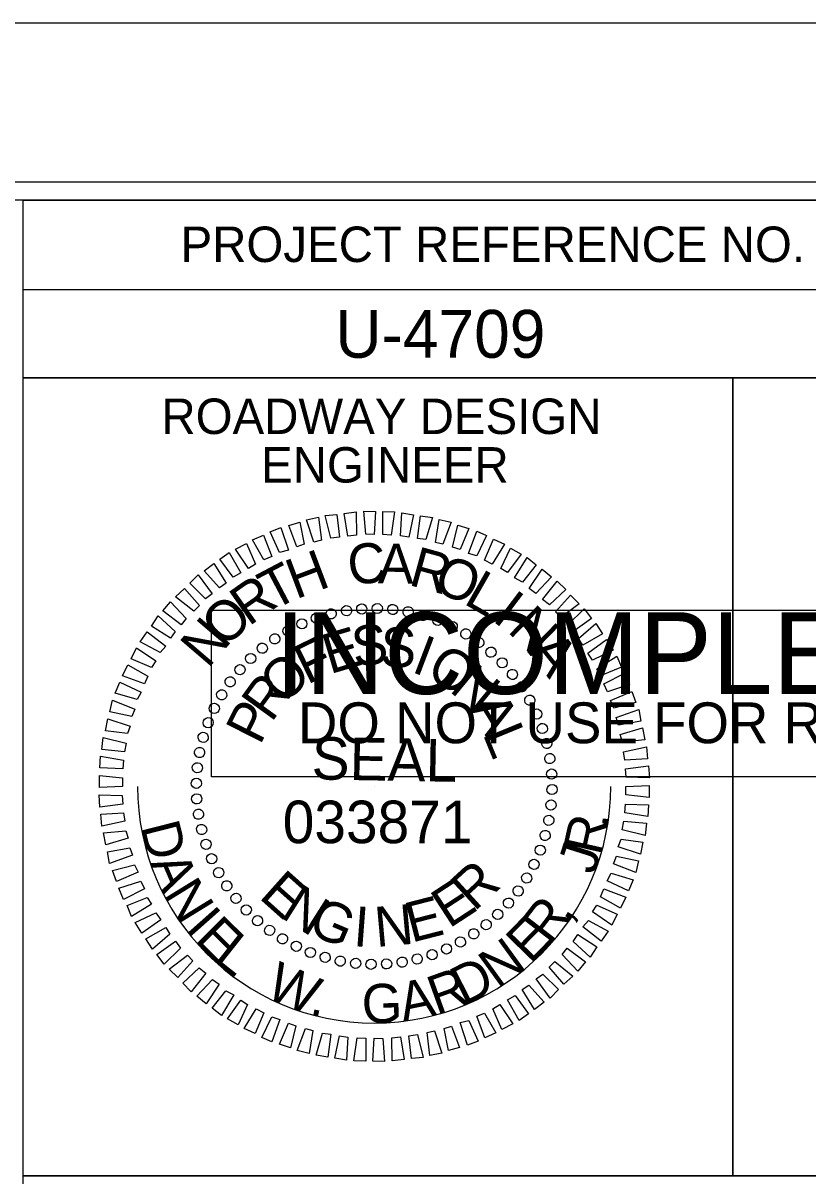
# Model space of a CAD drawing. Extents: x 958711 to 962106, y 831169 to 840840.
# Drawn here: x 960177.7 to 960288.4, y 835779.9 to 835942.4 of the extents above; entities that cross this region are included whole.
import ezdxf

# ---------------------------------------------------------------- set-up
doc = ezdxf.new("R2010")
doc.units = 0
for name, color, linetype in [('Scratch_Level_0', 7, 'Continuous'), ('Sheet Data Field CELL', 7, 'Continuous'), ('Sheet Plot Border Inside CELL', 7, 'Continuous'), ('Sheet Plot Border Outside CELL', 7, 'Continuous'), ('Sheet Professional Seal CELL', 7, 'Continuous'), ('Sheet Profile Grid Minor CELL', 7, 'Continuous'), ('Sheet Sticker Exception Certification CELL', 7, 'Continuous'), ('Sheet Sticker Incomplete CELL', 7, 'Continuous'), ('Sheet Typical CELL', 7, 'Continuous')]:
    doc.layers.add(name, color=color, linetype=linetype)

msp = doc.modelspace()

# ---------------------------------------------------------------- linework, layer by layer
at = {"layer": 'Scratch_Level_0'}
msp.add_arc((960227.25, 835834.78), 33.36, 180, 360, dxfattribs=at)
at = {"layer": 'Sheet Plot Border Inside CELL'}
msp.add_lwpolyline([(960390.3, 835919.97), (958723.8, 835919.97), (958723.8, 834864.87), (960390.3, 834864.87)], close=True, dxfattribs=at)
at = {"layer": 'Sheet Plot Border Outside CELL'}
msp.add_lwpolyline([(960394.8, 835942.42), (958710.8, 835942.42), (958710.8, 834842.42), (960394.8, 834842.42)], close=True, dxfattribs=at)
at = {"layer": 'Sheet Professional Seal CELL'}
for p, q in [((960223.35, 835859.53), (960223.35, 835859.53)), ((960225.5, 835859.83), (960225.5, 835859.83)), ((960227.7, 835859.88), (960227.7, 835859.88)), ((960229.9, 835859.73), (960229.9, 835859.73)), ((960232.05, 835859.38), (960232.05, 835859.38)), ((960219.05, 835858.53), (960219.05, 835858.53)), ((960221.15, 835859.13), (960221.15, 835859.13)), ((960234.15, 835858.93), (960234.15, 835858.93)), ((960236.25, 835858.23), (960236.25, 835858.23)), ((960215.1, 835856.73), (960215.1, 835856.73)), ((960217.05, 835857.73), (960217.05, 835857.73)), ((960238.25, 835857.33), (960238.25, 835857.33)), ((960240.2, 835856.33), (960240.2, 835856.33)), ((960213.2, 835855.58), (960213.2, 835855.58)), ((960242, 835855.08), (960242, 835855.08)), ((960211.45, 835854.33), (960211.45, 835854.33)), ((960243.75, 835853.73), (960243.75, 835853.73)), ((960208.3, 835851.28), (960208.3, 835851.28)), ((960209.8, 835852.83), (960209.8, 835852.83)), ((960245.3, 835852.23), (960245.3, 835852.23)), ((960246.8, 835850.58), (960246.8, 835850.58)), ((960206.95, 835849.53), (960206.95, 835849.53)), ((960248.05, 835848.83), (960248.05, 835848.83)), ((960205.7, 835847.73), (960205.7, 835847.73)), ((960249.2, 835846.93), (960249.2, 835846.93)), ((960204.7, 835845.78), (960204.7, 835845.78)), ((960250.2, 835844.98), (960250.2, 835844.98)), ((960203.8, 835843.78), (960203.8, 835843.78)), ((960203.1, 835841.68), (960203.1, 835841.68)), ((960251, 835842.98), (960251, 835842.98)), ((960251.6, 835840.88), (960251.6, 835840.88)), ((960202.65, 835839.58), (960202.65, 835839.58)), ((960252, 835838.68), (960252, 835838.68)), ((960202.3, 835837.43), (960202.3, 835837.43)), ((960202.15, 835835.23), (960202.15, 835835.23)), ((960252.3, 835836.53), (960252.3, 835836.53)), ((960227.25, 835834.78), (960227.25, 835834.78)), ((960252.35, 835834.33), (960252.35, 835834.33)), ((960202.2, 835833.03), (960202.2, 835833.03)), ((960252.2, 835832.13), (960252.2, 835832.13)), ((960202.5, 835830.88), (960202.5, 835830.88)), ((960202.9, 835828.68), (960202.9, 835828.68)), ((960251.85, 835829.98), (960251.85, 835829.98)), ((960251.4, 835827.88), (960251.4, 835827.88)), ((960203.5, 835826.58), (960203.5, 835826.58)), ((960250.7, 835825.78), (960250.7, 835825.78)), ((960204.3, 835824.58), (960204.3, 835824.58)), ((960249.8, 835823.78), (960249.8, 835823.78)), ((960205.3, 835822.63), (960205.3, 835822.63)), ((960206.45, 835820.73), (960206.45, 835820.73)), ((960248.8, 835821.83), (960248.8, 835821.83)), ((960207.7, 835818.98), (960207.7, 835818.98)), ((960247.55, 835820.03), (960247.55, 835820.03)), ((960209.2, 835817.33), (960209.2, 835817.33)), ((960246.2, 835818.28), (960246.2, 835818.28)), ((960210.75, 835815.83), (960210.75, 835815.83)), ((960244.7, 835816.73), (960244.7, 835816.73)), ((960212.5, 835814.48), (960212.5, 835814.48)), ((960241.3, 835813.98), (960241.3, 835813.98)), ((960243.05, 835815.23), (960243.05, 835815.23)), ((960214.3, 835813.23), (960214.3, 835813.23)), ((960216.25, 835812.23), (960216.25, 835812.23)), ((960239.4, 835812.83), (960239.4, 835812.83)), ((960218.25, 835811.33), (960218.25, 835811.33)), ((960220.35, 835810.63), (960220.35, 835810.63)), ((960235.45, 835811.03), (960235.45, 835811.03)), ((960237.45, 835811.83), (960237.45, 835811.83)), ((960222.45, 835810.18), (960222.45, 835810.18)), ((960224.6, 835809.83), (960224.6, 835809.83)), ((960226.8, 835809.68), (960226.8, 835809.68)), ((960229, 835809.73), (960229, 835809.73)), ((960231.15, 835810.03), (960231.15, 835810.03)), ((960233.35, 835810.43), (960233.35, 835810.43))]:
    msp.add_line(p, q, dxfattribs=at)
for points in [[(960218.75, 835869.23), (960217.7, 835872.38), (960219.4, 835872.73), (960219.8, 835869.48)], [(960221.15, 835869.78), (960220.35, 835872.98), (960222, 835873.13), (960222.35, 835869.93)], [(960223.55, 835870.08), (960223, 835873.28), (960224.7, 835873.48), (960224.75, 835870.23)], [(960226.05, 835870.33), (960225.8, 835873.58), (960227.45, 835873.53), (960227.25, 835870.28)], [(960228.45, 835870.28), (960228.45, 835873.53), (960230.1, 835873.48), (960229.65, 835870.23)], [(960230.95, 835870.13), (960231.15, 835873.38), (960232.8, 835873.08), (960232.15, 835869.93)], [(960233.35, 835869.73), (960233.8, 835872.93), (960235.45, 835872.68), (960234.55, 835869.58)], [(960235.9, 835869.18), (960236.4, 835872.43), (960238.1, 835872.03), (960236.95, 835868.93)], [(960213.9, 835867.78), (960212.6, 835870.68), (960214.1, 835871.28), (960215.15, 835868.08)], [(960216.35, 835868.58), (960215.2, 835871.58), (960216.75, 835872.03), (960217.4, 835868.93)], [(960238.3, 835868.53), (960239.05, 835871.63), (960240.6, 835871.13), (960239.35, 835868.18)], [(960240.55, 835867.63), (960241.7, 835870.78), (960243.1, 835870.18), (960241.7, 835867.28)], [(960211.7, 835866.73), (960210.1, 835869.53), (960211.65, 835870.23), (960212.8, 835867.18)], [(960242.8, 835866.68), (960244.05, 835869.63), (960245.6, 835868.93), (960243.9, 835866.13)], [(960207.35, 835864.28), (960205.5, 835866.83), (960206.8, 835867.78), (960208.45, 835864.88)], [(960209.55, 835865.53), (960207.7, 835868.23), (960209.25, 835869.03), (960210.5, 835866.13)], [(960245.1, 835865.53), (960246.45, 835868.38), (960247.95, 835867.53), (960246.05, 835864.93)], [(960205.45, 835862.78), (960203.3, 835865.18), (960204.65, 835866.23), (960206.4, 835863.43)], [(960247.05, 835864.18), (960248.8, 835867.08), (960250.1, 835866.03), (960248.15, 835863.58)], [(960203.45, 835861.23), (960201.25, 835863.43), (960202.45, 835864.63), (960204.4, 835861.93)], [(960249.1, 835862.68), (960250.95, 835865.43), (960252.25, 835864.33), (960250.05, 835861.98)], [(960201.8, 835859.48), (960199.25, 835861.53), (960200.5, 835862.68), (960202.6, 835860.28)], [(960251, 835861.13), (960253.05, 835863.73), (960254.25, 835862.53), (960251.95, 835860.38)], [(960252.8, 835859.38), (960254.95, 835861.73), (960256.15, 835860.53), (960253.55, 835858.58)], [(960200.05, 835857.58), (960197.45, 835859.53), (960198.55, 835860.83), (960200.75, 835858.48)], [(960254.55, 835857.58), (960256.85, 835859.83), (960257.9, 835858.48), (960255.25, 835856.58)], [(960198.55, 835855.68), (960195.85, 835857.38), (960196.8, 835858.83), (960199.2, 835856.63)], [(960197.05, 835853.68), (960194.25, 835855.18), (960195.25, 835856.58), (960197.85, 835854.58)], [(960256.05, 835855.63), (960258.5, 835857.73), (960259.45, 835856.28), (960256.65, 835854.68)], [(960257.35, 835853.58), (960260, 835855.48), (960260.95, 835853.98), (960258.05, 835852.58)], [(960195.85, 835851.53), (960193, 835852.78), (960193.75, 835854.33), (960196.45, 835852.48)], [(960258.65, 835851.38), (960261.45, 835853.13), (960262.1, 835851.58), (960259.25, 835850.43)], [(960194.85, 835849.23), (960191.75, 835850.38), (960192.5, 835851.93), (960195.35, 835850.33)], [(960259.65, 835849.23), (960262.6, 835850.73), (960263.25, 835849.13), (960260.15, 835848.13)], [(960193.85, 835847.03), (960190.75, 835847.93), (960191.4, 835849.48), (960194.4, 835848.08)], [(960260.55, 835846.88), (960263.6, 835848.18), (960264.15, 835846.63), (960261.05, 835845.83)], [(960193.1, 835844.63), (960190, 835845.28), (960190.35, 835846.93), (960193.5, 835845.68)], [(960261.35, 835844.48), (960264.55, 835845.63), (960264.85, 835843.98), (960261.7, 835843.43)], [(960192.45, 835842.23), (960189.35, 835842.63), (960189.7, 835844.33), (960192.85, 835843.28)], [(960192.05, 835839.68), (960188.85, 835839.98), (960189.05, 835841.68), (960192.3, 835840.88)], [(960261.95, 835842.08), (960265.1, 835843.03), (960265.4, 835841.33), (960262.25, 835841.03)], [(960262.4, 835839.68), (960265.65, 835840.38), (960265.8, 835838.68), (960262.6, 835838.48)], [(960191.8, 835837.28), (960188.55, 835837.38), (960188.65, 835839.03), (960191.9, 835838.48)], [(960262.7, 835837.28), (960265.95, 835837.68), (960266.05, 835835.98), (960262.8, 835836.08)], [(960191.75, 835834.78), (960188.5, 835834.63), (960188.5, 835836.33), (960191.75, 835835.98)], [(960191.8, 835832.28), (960188.55, 835831.88), (960188.45, 835833.58), (960191.7, 835833.48)], [(960262.75, 835834.78), (960266, 835834.93), (960266, 835833.23), (960262.75, 835833.58)], [(960262.7, 835832.28), (960265.95, 835832.18), (960265.85, 835830.53), (960262.6, 835831.08)], [(960192.1, 835829.88), (960188.85, 835829.18), (960188.7, 835830.88), (960191.9, 835831.08)], [(960192.55, 835827.48), (960189.4, 835826.53), (960189.1, 835828.23), (960192.25, 835828.53)], [(960262.45, 835829.88), (960265.65, 835829.58), (960265.45, 835827.88), (960262.2, 835828.68)], [(960262.05, 835827.33), (960265.15, 835826.93), (960264.8, 835825.23), (960261.65, 835826.28)], [(960193.15, 835825.08), (960189.95, 835823.93), (960189.65, 835825.58), (960192.8, 835826.13)], [(960193.95, 835822.68), (960190.9, 835821.38), (960190.35, 835822.93), (960193.45, 835823.73)], [(960261.4, 835824.93), (960264.5, 835824.28), (960264.15, 835822.63), (960261, 835823.88)], [(960260.65, 835822.53), (960263.75, 835821.63), (960263.1, 835820.08), (960260.1, 835821.48)], [(960194.85, 835820.33), (960191.9, 835818.83), (960191.25, 835820.43), (960194.35, 835821.43)], [(960195.85, 835818.18), (960193.05, 835816.43), (960192.4, 835817.98), (960195.25, 835819.13)], [(960259.65, 835820.33), (960262.75, 835819.18), (960262, 835817.63), (960259.15, 835819.23)], [(960258.65, 835818.03), (960261.5, 835816.78), (960260.75, 835815.23), (960258.05, 835817.08)], [(960197.15, 835815.98), (960194.5, 835814.08), (960193.55, 835815.58), (960196.45, 835816.98)], [(960257.45, 835815.88), (960260.25, 835814.38), (960259.25, 835812.98), (960256.65, 835814.98)], [(960198.45, 835813.93), (960196, 835811.83), (960195.05, 835813.28), (960197.85, 835814.88)], [(960255.95, 835813.88), (960258.65, 835812.18), (960257.7, 835810.73), (960255.3, 835812.93)], [(960199.95, 835811.98), (960197.65, 835809.73), (960196.6, 835811.08), (960199.25, 835812.98)], [(960201.7, 835810.18), (960199.55, 835807.83), (960198.35, 835809.03), (960200.95, 835810.98)], [(960254.45, 835811.98), (960257.05, 835810.03), (960255.95, 835808.73), (960253.75, 835811.08)], [(960203.5, 835808.43), (960201.45, 835805.83), (960200.25, 835807.03), (960202.55, 835809.18)], [(960252.7, 835810.08), (960255.25, 835808.03), (960254, 835806.88), (960251.9, 835809.28)], [(960205.4, 835806.88), (960203.55, 835804.13), (960202.25, 835805.23), (960204.45, 835807.58)], [(960251.05, 835808.33), (960253.25, 835806.13), (960252.05, 835804.93), (960250.1, 835807.63)], [(960207.45, 835805.38), (960205.7, 835802.48), (960204.4, 835803.53), (960206.35, 835805.98)], [(960249.05, 835806.78), (960251.2, 835804.38), (960249.85, 835803.33), (960248.1, 835806.13)], [(960209.4, 835804.03), (960208.05, 835801.18), (960206.55, 835802.03), (960208.45, 835804.63)], [(960247.15, 835805.28), (960249, 835802.73), (960247.7, 835801.78), (960246.05, 835804.68)], [(960211.7, 835802.88), (960210.45, 835799.93), (960208.9, 835800.63), (960210.6, 835803.43)], [(960242.8, 835802.83), (960244.4, 835800.03), (960242.85, 835799.33), (960241.7, 835802.38)], [(960244.95, 835804.03), (960246.8, 835801.33), (960245.25, 835800.53), (960244, 835803.43)], [(960213.95, 835801.93), (960212.8, 835798.78), (960211.4, 835799.38), (960212.8, 835802.28)], [(960216.2, 835801.03), (960215.45, 835797.93), (960213.9, 835798.43), (960215.15, 835801.38)], [(960238.15, 835800.98), (960239.3, 835797.98), (960237.75, 835797.53), (960237.1, 835800.63)], [(960240.6, 835801.78), (960241.9, 835798.88), (960240.4, 835798.28), (960239.35, 835801.48)], [(960218.6, 835800.38), (960218.1, 835797.13), (960216.4, 835797.53), (960217.55, 835800.63)], [(960221.15, 835799.83), (960220.7, 835796.63), (960219.05, 835796.88), (960219.95, 835799.98)], [(960223.55, 835799.43), (960223.35, 835796.18), (960221.7, 835796.48), (960222.35, 835799.63)], [(960226.05, 835799.28), (960226.05, 835796.03), (960224.4, 835796.08), (960224.85, 835799.33)], [(960228.45, 835799.23), (960228.7, 835795.98), (960227.05, 835796.03), (960227.25, 835799.28)], [(960230.95, 835799.48), (960231.5, 835796.28), (960229.8, 835796.08), (960229.75, 835799.33)], [(960233.35, 835799.78), (960234.15, 835796.58), (960232.5, 835796.43), (960232.15, 835799.63)], [(960235.75, 835800.33), (960236.8, 835797.18), (960235.1, 835796.83), (960234.7, 835800.08)]]:
    msp.add_lwpolyline(points, close=True, dxfattribs=at)
for centre, major_axis in [((960221.18, 835859.12), (-0.174, 0.699)), ((960223.33, 835859.56), (-0.113, 0.711)), ((960225.5, 835859.8), (-0.05, 0.718)), ((960227.69, 835859.86), (0.013, 0.72)), ((960229.87, 835859.73), (0.075, 0.716)), ((960232.04, 835859.4), (0.137, 0.707)), ((960234.16, 835858.89), (0.198, 0.692)), ((960217.05, 835857.7), (-0.293, 0.658)), ((960219.09, 835858.5), (-0.234, 0.681)), ((960236.24, 835858.2), (0.258, 0.672)), ((960238.25, 835857.33), (0.316, 0.647)), ((960213.23, 835855.58), (-0.403, 0.597)), ((960215.09, 835856.72), (-0.349, 0.63)), ((960240.17, 835856.28), (0.371, 0.617)), ((960211.47, 835854.27), (-0.453, 0.56)), ((960241.99, 835855.07), (0.423, 0.582)), ((960243.71, 835853.71), (0.472, 0.543)), ((960209.83, 835852.82), (-0.5, 0.518)), ((960245.29, 835852.21), (0.518, 0.5)), ((960208.32, 835851.24), (-0.543, 0.472)), ((960246.74, 835850.57), (0.56, 0.453)), ((960206.96, 835849.53), (-0.582, 0.423)), ((960248.04, 835848.81), (0.597, 0.403)), ((960205.75, 835847.7), (-0.617, 0.371)), ((960204.71, 835845.78), (-0.647, 0.316)), ((960249.19, 835846.94), (0.63, 0.349)), ((960250.16, 835844.98), (0.658, 0.293)), ((960203.84, 835843.77), (-0.672, 0.258)), ((960250.97, 835842.95), (0.681, 0.234)), ((960203.14, 835841.7), (-0.692, 0.198)), ((960251.59, 835840.85), (0.699, 0.174)), ((960202.63, 835839.57), (-0.707, 0.137)), ((960252.02, 835838.71), (0.711, 0.113)), ((960202.31, 835837.41), (-0.716, 0.075)), ((960252.27, 835836.53), (0.718, 0.05)), ((960202.18, 835835.22), (-0.72, 0.013)), ((960252.33, 835834.35), (0.72, -0.013)), ((960202.23, 835833.03), (-0.718, -0.05)), ((960252.19, 835832.16), (0.716, -0.075)), ((960202.48, 835830.86), (-0.711, -0.113)), ((960251.87, 835830), (0.707, -0.137)), ((960202.92, 835828.72), (-0.699, -0.174)), ((960251.36, 835827.87), (0.692, -0.198)), ((960203.54, 835826.62), (-0.681, -0.234)), ((960204.34, 835824.58), (-0.658, -0.293)), ((960250.67, 835825.8), (0.672, -0.258)), ((960249.79, 835823.79), (0.647, -0.316)), ((960205.32, 835822.62), (-0.63, -0.349)), ((960248.75, 835821.87), (0.617, -0.371)), ((960206.46, 835820.76), (-0.597, -0.403)), ((960247.54, 835820.04), (0.582, -0.423)), ((960207.76, 835819), (-0.56, -0.453)), ((960246.18, 835818.33), (0.543, -0.472)), ((960209.21, 835817.36), (-0.518, -0.5)), ((960244.67, 835816.74), (0.5, -0.518)), ((960210.8, 835815.86), (-0.472, -0.543)), ((960243.04, 835815.29), (0.453, -0.56)), ((960212.51, 835814.49), (-0.423, -0.582)), ((960214.33, 835813.29), (-0.371, -0.617)), ((960241.28, 835813.99), (0.403, -0.597)), ((960216.26, 835812.24), (-0.316, -0.647)), ((960237.45, 835811.87), (0.293, -0.658)), ((960239.41, 835812.85), (0.349, -0.63)), ((960218.26, 835811.37), (-0.258, -0.672)), ((960220.34, 835810.68), (-0.198, -0.692)), ((960222.47, 835810.16), (-0.137, -0.707)), ((960224.63, 835809.84), (-0.075, -0.716)), ((960231.18, 835810.01), (0.113, -0.711)), ((960233.32, 835810.45), (0.174, -0.699)), ((960235.42, 835811.07), (0.234, -0.681)), ((960226.81, 835809.71), (-0.013, -0.72)), ((960229, 835809.76), (0.05, -0.718))]:
    msp.add_ellipse(centre, major_axis=major_axis, ratio=0.999708, dxfattribs=at)
at = {"layer": 'Sheet Sticker Exception Certification CELL'}
for p, q in [((960177.75, 835756.37), (960177.75, 835779.87)), ((960177.75, 835779.87), (960377.79, 835779.87))]:
    msp.add_line(p, q, dxfattribs=at)
at = {"layer": 'Sheet Sticker Incomplete CELL'}
msp.add_lwpolyline([(960204.3, 835836.12), (960204.3, 835859.62), (960351.3, 835859.62), (960351.3, 835836.12)], close=True, dxfattribs=at)
at = {"layer": 'Sheet Typical CELL'}
for p, q in [((960177.75, 835904.87), (960377.8, 835904.87)), ((960277.8, 835892.37), (960277.8, 835779.92))]:
    msp.add_line(p, q, dxfattribs=at)
for points in [[(960377.8, 835917.42), (958877.8, 835917.42), (958877.8, 834867.42), (960377.8, 834867.42)], [(960177.75, 835917.42), (960377.8, 835917.42), (960377.8, 835892.37), (960177.75, 835892.37)], [(960177.75, 835892.37), (960277.8, 835892.37), (960277.8, 835779.87), (960177.75, 835779.87)], [(960277.8, 835892.37), (960377.8, 835892.37), (960377.8, 835779.87), (960277.8, 835779.87)]]:
    msp.add_lwpolyline(points, close=True, dxfattribs=at)

# ---------------------------------------------------------------- texts
at = {"layer": 'Sheet Data Field CELL'}
msp.add_text('U-4709', height=6.75, dxfattribs=at).set_placement((960221.78, 835895.22))
at = {"layer": 'Sheet Professional Seal CELL'}
for s, height, rotation, p in [('C', 5.64, 6.2199, (960223.8, 835863.13)), ('H', 5.64, 20.6195, (960216.2, 835861.13)), ('A', 5.64, 359.0203, (960227.75, 835863.43)), ('R', 5.64, 344.6211, (960231.95, 835863.23)), ('T', 5.64, 27.8198, (960212.95, 835859.48)), ('O', 5.64, 337.4212, (960235.3, 835862.48)), ('L', 5.64, 330.2209, (960239.7, 835860.63)), ('R', 5.64, 35.0205, (960209.55, 835857.28)), ('O', 5.64, 42.2217, (960206.1, 835854.18)), ('I', 5.64, 323.0201, (960243.75, 835858.23)), ('N', 5.64, 315.8189, (960245.9, 835856.68)), ('N', 5.64, 49.4235, (960203.8, 835851.28)), ('S', 5.64, 7.2556, (960224.45, 835851.63)), ('E', 5.64, 16.6111, (960221, 835850.58)), ('S', 5.64, 357.9004, (960228.05, 835851.68)), ('F', 5.64, 25.967, (960217.8, 835849.08)), ('I', 5.64, 339.1896, (960232.35, 835850.98)), ('A', 5.64, 308.6172, (960248.85, 835853.73)), ('O', 5.64, 44.6812, (960214.5, 835846.13)), ('O', 5.64, 329.8335, (960234.35, 835850.28)), ('N', 5.64, 320.4766, (960237.7, 835848.28)), ('R', 5.64, 54.0397, (960212.75, 835843.68)), ('P', 5.64, 63.3989, (960211.15, 835840.48)), ('A', 5.64, 301.7603, (960240.55, 835845.68)), ('L', 5.64, 292.4008, (960242.5, 835842.23)), ('SEAL', 5.998, 359, (960218.4, 835835.78)), ('R', 5.64, 42.4814, (960241.35, 835817.03)), ('E', 5.64, 318.2769, (960210.85, 835819.13)), ('N', 5.64, 327.634, (960213.85, 835816.43)), ('E', 5.64, 33.1241, (960237.8, 835814.68)), ('G', 5.64, 336.9902, (960217.65, 835814.18)), ('E', 5.64, 14.4118, (960232.5, 835812.73)), ('I', 5.64, 355.7012, (960224.2, 835812.28)), ('N', 5.64, 5.0564, (960227.55, 835812.13))]:
    msp.add_text(s, height=height, rotation=rotation, dxfattribs=at).set_placement(p)
at = {"layer": 'Sheet Profile Grid Minor CELL'}
msp.add_text('033871', height=5.998, dxfattribs=at).set_placement((960214.35, 835826.78))
for s, rotation, p in [('R', 77.3541, (960259.22, 835824.88)), ('.', 84.2805, (960260.18, 835828.81)), ('D', 284.2682, (960194.26, 835829.14)), ('J', 72.4855, (960258.27, 835822.2)), ('A', 293.4128, (960195.58, 835823.97)), ('N', 301.5986, (960197.44, 835819.57)), ('R', 52.3788, (960252.05, 835812.31)), ('I', 311.5304, (960200.51, 835814.66)), ('E', 315.0508, (960201.8, 835813.05)), ('E', 45.7958, (960249.31, 835809.61)), (',', 59.3052, (960254.58, 835815.46)), ('L', 321.6338, (960204.46, 835810.28)), ('N', 35.8641, (960244.64, 835806.19)), ('W', 336.8891, (960211.71, 835805.14)), ('D', 26.7195, (960239.87, 835803.79)), ('A', 11.6072, (960231.36, 835801.57)), ('R', 19.793, (960236.04, 835802.49)), ('G', 1.6755, (960225.57, 835801.36)), ('.', 348.4952, (960217.99, 835802.62))]:
    msp.add_text(s, height=5.5, rotation=rotation, dxfattribs=at).set_placement(p)
at = {"layer": 'Sheet Sticker Incomplete CELL'}
for s, height, p in [('INCOMPLETE PLANS', 11.52, (960213.25, 835847.82)), ('DO NOT USE FOR R/W ACQUISITION', 5.76, (960216.5, 835840.87))]:
    msp.add_text(s, height=height, dxfattribs=at).set_placement(p)
at = {"layer": 'Sheet Typical CELL'}
for s, height, p in [('PROJECT REFERENCE NO.', 5.0001, (960199.95, 835908.72)), ('ROADWAY DESIGN', 5.0001, (960197.25, 835884.47)), ('ENGINEER', 5, (960211.3, 835877.62))]:
    msp.add_text(s, height=height, dxfattribs=at).set_placement(p)

doc.saveas('drawing.dxf')
